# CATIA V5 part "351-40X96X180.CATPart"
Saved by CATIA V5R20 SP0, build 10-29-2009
Part number: 351-40X96X180
Definition: NONE
Nomenclature: 351-40X96X180
Source: Unknown
Description: 351-40X96X180
Bounding box of the stored display mesh (mm): x -8 to 172, y -26 to 26, z -26 to 26
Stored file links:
  C:\Users\Utente\Desktop\IO LAVORO\3D X SITO CF\X SITO\PLASTICA\351\351-40X96X180.CATPart

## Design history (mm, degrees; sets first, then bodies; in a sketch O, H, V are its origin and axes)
Body1 "351-40X96X180" (main body)
  Solid1: solid without history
